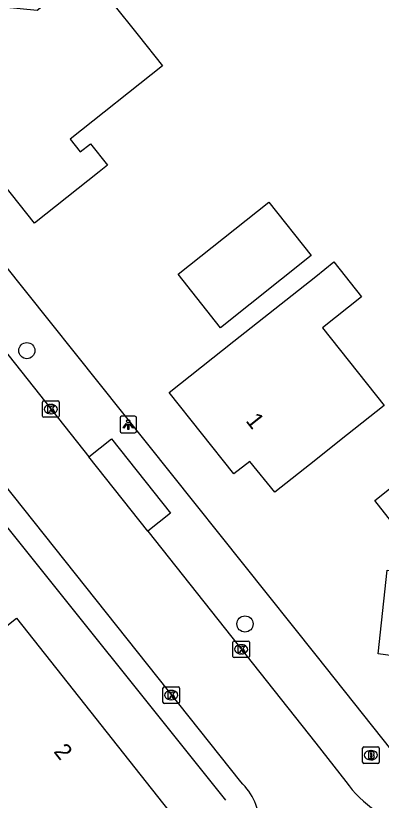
# Model space of a CAD drawing. Extents: x 159503 to 160347, y 382525 to 383272.
# Drawn here: x 159981.84 to 160003.97, y 383065.19 to 383112.66 of the extents above; entities that cross this region are included whole.
import ezdxf

# ---------------------------------------------------------------- set-up
doc = ezdxf.new("R2010")
doc.units = 0
for name, color, linetype in [('IMGEO_Boom', 7, 'Continuous'), ('IMGEO_Brandkraan', 7, 'Continuous'), ('IMGEO_Kolk', 7, 'Continuous'), ('IMGEO_Lichtpunt', 7, 'Continuous'), ('IMGEO_Pand', 7, 'Continuous'), ('IMGEO_Pand_nummerreeks', 7, 'Continuous'), ('IMGEO_Rijbaan_lokaal_open', 7, 'Continuous')]:
    doc.layers.add(name, color=color, linetype=linetype)

msp = doc.modelspace()

# ---------------------------------------------------------------- linework, layer by layer
at = {"layer": 'IMGEO_Boom'}
for centre in [(159982.51, 383092.398), (159995.72, 383075.858)]:
    msp.add_circle(centre, 0.489, dxfattribs=at)
at = {"layer": 'IMGEO_Brandkraan'}
for p, q in [((160002.843, 383067.49), (160002.843, 383068.342)), ((160002.918, 383068.416), (160003.77, 383068.416)), ((160003.331, 383068.196), (160003.356, 383068.196)), ((160003.844, 383068.342), (160003.844, 383067.49)), ((160003.354, 383067.636), (160003.329, 383067.636)), ((160003.77, 383067.416), (160002.918, 383067.416))]:
    msp.add_line(p, q, dxfattribs=at)
for points in [[(160002.843, 383067.49), (160002.843, 383068.342)], [(160002.918, 383068.416), (160003.77, 383068.416)], [(160003.191, 383068.116), (160003.191, 383067.716), (160003.404, 383067.716)], [(160003.422, 383068.116), (160003.191, 383068.116)], [(160003.844, 383068.342), (160003.844, 383067.49)], [(160003.37, 383068.035), (160003.316, 383068.035), (160003.316, 383067.959)], [(160003.316, 383067.959), (160003.369, 383067.959)], [(160003.378, 383067.883), (160003.316, 383067.883), (160003.316, 383067.802)], [(160003.316, 383067.802), (160003.378, 383067.802)], [(160003.77, 383067.416), (160002.918, 383067.416)]]:
    msp.add_lwpolyline(points, dxfattribs=at)
for centre, radius, start, end in [((160002.92, 383068.34), 0.0765, 91.552, 178.448), ((160002.92, 383068.34), 0.0765, 91.552, 178.448), ((160003.426, 383067.971), 0.145, 59.4692, 91.5367), ((160003.451, 383068.018), 0.0922, 285.5137, 58.1501), ((160003.768, 383068.34), 0.0765, 1.552, 88.448), ((160003.768, 383068.34), 0.0765, 1.552, 88.448), ((160003.371, 383067.997), 0.0379, 267.8285, 90.9355), ((160003.379, 383067.842), 0.0404, 269.8759, 90.5077), ((160003.41, 383067.967), 0.251, 268.6676, 293.5347), ((160003.456, 383067.826), 0.105, 301.3115, 78.989), ((160002.92, 383067.492), 0.0765, 181.552, 268.448), ((160002.92, 383067.492), 0.0765, 181.552, 268.448), ((160003.768, 383067.492), 0.0765, 271.552, 358.448), ((160003.768, 383067.492), 0.0765, 271.552, 358.448)]:
    msp.add_arc(centre, radius, start, end, dxfattribs=at)
for centre, major_axis, ratio, start_param, end_param in [((160003.33, 383067.916), (-0.387, 0.002), 0.722429, 4.712389, 7.853982), ((160003.355, 383067.916), (-0.39, 0.002), 0.717154, 1.570796, 4.712389)]:
    msp.add_ellipse(centre, major_axis=major_axis, ratio=ratio, start_param=start_param, end_param=end_param, dxfattribs=at)
at = {"layer": 'IMGEO_Kolk'}
for p, q in [((159983.465, 383088.436), (159983.465, 383089.288)), ((159983.54, 383089.362), (159984.392, 383089.362)), ((159983.953, 383089.142), (159983.978, 383089.142)), ((159984.466, 383089.288), (159984.466, 383088.436)), ((159983.976, 383088.582), (159983.951, 383088.582)), ((159984.392, 383088.362), (159983.54, 383088.362)), ((159994.991, 383073.898), (159994.991, 383074.75)), ((159995.066, 383074.824), (159995.918, 383074.824)), ((159995.992, 383074.75), (159995.992, 383073.898)), ((159995.479, 383074.604), (159995.504, 383074.604)), ((159995.918, 383073.824), (159995.066, 383073.824)), ((159995.502, 383074.044), (159995.477, 383074.044)), ((159990.754, 383071.127), (159990.754, 383071.979)), ((159990.829, 383072.053), (159991.681, 383072.053)), ((159991.755, 383071.979), (159991.755, 383071.127)), ((159991.242, 383071.833), (159991.267, 383071.833)), ((159991.681, 383071.053), (159990.829, 383071.053)), ((159991.265, 383071.273), (159991.24, 383071.273))]:
    msp.add_line(p, q, dxfattribs=at)
for points in [[(159983.465, 383088.436), (159983.465, 383089.288)], [(159983.54, 383089.362), (159984.392, 383089.362)], [(159983.786, 383089.062), (159983.909, 383089.062), (159983.909, 383088.911), (159984.039, 383089.062), (159984.203, 383089.062), (159984.057, 383088.911), (159984.21, 383088.662), (159984.058, 383088.662), (159983.973, 383088.826), (159983.909, 383088.759), (159983.909, 383088.662), (159983.786, 383088.662), (159983.786, 383089.062)], [(159984.466, 383089.288), (159984.466, 383088.436)], [(159984.392, 383088.362), (159983.54, 383088.362)], [(159994.991, 383073.898), (159994.991, 383074.75)], [(159995.066, 383074.824), (159995.918, 383074.824)], [(159995.992, 383074.75), (159995.992, 383073.898)], [(159995.312, 383074.524), (159995.435, 383074.524), (159995.435, 383074.373), (159995.565, 383074.524), (159995.729, 383074.524), (159995.583, 383074.373), (159995.736, 383074.124), (159995.584, 383074.124), (159995.499, 383074.288), (159995.435, 383074.221), (159995.435, 383074.124), (159995.312, 383074.124), (159995.312, 383074.524)], [(159995.918, 383073.824), (159995.066, 383073.824)], [(159990.754, 383071.127), (159990.754, 383071.979)], [(159990.829, 383072.053), (159991.681, 383072.053)], [(159991.755, 383071.979), (159991.755, 383071.127)], [(159991.075, 383071.753), (159991.198, 383071.753), (159991.198, 383071.602), (159991.328, 383071.753), (159991.492, 383071.753), (159991.346, 383071.602), (159991.499, 383071.353), (159991.347, 383071.353), (159991.262, 383071.517), (159991.198, 383071.45), (159991.198, 383071.353), (159991.075, 383071.353), (159991.075, 383071.753)], [(159991.681, 383071.053), (159990.829, 383071.053)]]:
    msp.add_lwpolyline(points, dxfattribs=at)
for centre, start, end in [((159983.542, 383089.286), 91.552, 178.448), ((159983.542, 383089.286), 91.552, 178.448), ((159984.39, 383089.286), 1.552, 88.448), ((159984.39, 383089.286), 1.552, 88.448), ((159983.542, 383088.438), 181.552, 268.448), ((159983.542, 383088.438), 181.552, 268.448), ((159984.39, 383088.438), 271.552, 358.448), ((159984.39, 383088.438), 271.552, 358.448), ((159995.068, 383074.748), 91.552, 178.448), ((159995.068, 383074.748), 91.552, 178.448), ((159995.916, 383074.748), 1.552, 88.448), ((159995.916, 383074.748), 1.552, 88.448), ((159995.068, 383073.9), 181.552, 268.448), ((159995.068, 383073.9), 181.552, 268.448), ((159995.916, 383073.9), 271.552, 358.448), ((159995.916, 383073.9), 271.552, 358.448), ((159990.831, 383071.977), 91.552, 178.448), ((159990.831, 383071.977), 91.552, 178.448), ((159991.679, 383071.977), 1.552, 88.448), ((159991.679, 383071.977), 1.552, 88.448), ((159990.831, 383071.129), 181.552, 268.448), ((159990.831, 383071.129), 181.552, 268.448), ((159991.679, 383071.129), 271.552, 358.448), ((159991.679, 383071.129), 271.552, 358.448)]:
    msp.add_arc(centre, 0.0765, start, end, dxfattribs=at)
for centre, major_axis, ratio, start_param, end_param in [((159983.952, 383088.862), (-0.387, 0.002), 0.722429, 4.712389, 7.853982), ((159983.977, 383088.862), (-0.39, 0.002), 0.717154, 1.570796, 4.712389), ((159995.478, 383074.324), (-0.387, 0.002), 0.722429, 4.712389, 7.853982), ((159995.503, 383074.324), (-0.39, 0.002), 0.717154, 1.570796, 4.712389), ((159991.241, 383071.553), (-0.387, 0.002), 0.722429, 4.712389, 7.853982), ((159991.266, 383071.553), (-0.39, 0.002), 0.717154, 1.570796, 4.712389)]:
    msp.add_ellipse(centre, major_axis=major_axis, ratio=ratio, start_param=start_param, end_param=end_param, dxfattribs=at)
at = {"layer": 'IMGEO_Lichtpunt'}
for p, q in [((159988.155, 383088.328), (159988.155, 383087.521)), ((159988.155, 383088.328), (159988.155, 383087.521)), ((159989.057, 383088.423), (159988.249, 383088.423)), ((159989.057, 383088.423), (159988.249, 383088.423)), ((159989.151, 383087.521), (159989.151, 383088.328)), ((159989.151, 383087.521), (159989.151, 383088.328)), ((159988.249, 383087.427), (159989.057, 383087.427)), ((159988.249, 383087.427), (159989.057, 383087.427))]:
    msp.add_line(p, q, dxfattribs=at)
for points in [[(159988.529, 383087.992), (159988.568, 383087.964), (159988.38, 383087.702), (159988.342, 383087.729), (159988.529, 383087.992)], [(159988.741, 383087.964), (159988.779, 383087.991), (159988.966, 383087.729), (159988.927, 383087.701), (159988.741, 383087.964)], [(159988.631, 383087.944), (159988.678, 383087.944), (159988.678, 383087.622), (159988.631, 383087.622), (159988.631, 383087.944)]]:
    msp.add_lwpolyline(points, dxfattribs=at)
msp.add_circle((159988.654, 383088.126), 0.0994, dxfattribs=at)
for centre, start, end in [((159988.249, 383088.328), 90, 180), ((159988.249, 383088.328), 90, 180), ((159989.057, 383088.328), 0, 90), ((159989.057, 383088.328), 0, 90), ((159988.249, 383087.521), 180, 270), ((159988.249, 383087.521), 180, 270), ((159989.057, 383087.521), 270, 0), ((159989.057, 383087.521), 270, 360)]:
    msp.add_arc(centre, 0.0946, start, end, dxfattribs=at)
at = {"layer": 'IMGEO_Pand'}
for points in [[(159990.718, 383109.639), (159985.126, 383105.184), (159985.737, 383104.418), (159986.361, 383104.917), (159987.389, 383103.626), (159986.881, 383103.221), (159982.971, 383100.104), (159980.091, 383103.717), (159980.599, 383104.122), (159978.131, 383107.219), (159977.63, 383106.82), (159973.87, 383111.54), (159978.65, 383115.3), (159980.233, 383113.288), (159983.128, 383112.99), (159986.139, 383115.388), (159989.255, 383111.477), (159990.718, 383109.639)], [(159994.232, 383093.785), (159991.67, 383097.02), (159997.172, 383101.379), (159999.734, 383098.144), (159994.232, 383093.785)], [(160004.152, 383089.074), (160001.451, 383086.935), (160000, 383085.786), (159997.531, 383083.83), (159996.02, 383085.698), (159995.048, 383084.943), (159991.134, 383089.869), (159995.054, 383092.974), (160000, 383096.892), (160001.098, 383097.761), (160002.775, 383095.644), (160000.423, 383093.78), (160004.152, 383089.074)], [(160011.843, 383085.728), (160013.657, 383085.494), (160013.102, 383080.419), (160012.189, 383080.526), (160012.019, 383078.201), (160013.746, 383076.102), (160011.54, 383074.345), (160007.652, 383071.248), (160005.568, 383073.804), (160003.777, 383074.045), (160004.319, 383079.118), (160005.233, 383079.064), (160005.425, 383080.99), (160003.591, 383083.329), (160007.496, 383086.453), (160009.78, 383088.28), (160011.843, 383085.728)], [(159981.882, 383076.202), (159991.799, 383063.691), (159985.573, 383058.726), (159984.982, 383059.41), (159982.494, 383057.437), (159979.38, 383061.349), (159978.579, 383062.354), (159979.762, 383063.296), (159976.547, 383067.334), (159977.876, 383068.392), (159975.603, 383071.247), (159977.958, 383073.105), (159981.882, 383076.202)]]:
    msp.add_lwpolyline(points, dxfattribs=at)
at = {"layer": 'IMGEO_Rijbaan_lokaal_open'}
for points in [[(159969.339, 383112.369), (160000, 383073.962), (160006.879, 383065.344), (160051.214, 383033.728), (160053.92, 383031.798)], [(159995.46, 383066.299), (159962.836, 383107.311)], [(159980.273, 383093.518), (159986.263, 383085.963)], [(159986.263, 383085.963), (159987.638, 383087.052), (159991.2, 383082.569), (159989.829, 383081.465)], [(159989.829, 383081.465), (159986.263, 383085.963)], [(159994.564, 383065.187), (159980.466, 383082.767)], [(159989.829, 383081.465), (160000, 383068.637), (160001.834, 383066.323)]]:
    msp.add_lwpolyline(points, dxfattribs=at)
for centre, radius, start, end in [((159992.986, 383063.631), 3.638, 0.4181, 47.1521), ((160006.929, 383069.78), 6.157, 214.1587, 237.8896)]:
    msp.add_arc(centre, radius, start, end, dxfattribs=at)

# ---------------------------------------------------------------- texts
at = {"layer": 'IMGEO_Pand_nummerreeks'}
for s, rotation, p in [('1', 308.4692, (159995.725, 383088.144)), ('2', 308.4052, (159984.098, 383068.126))]:
    msp.add_text(s, height=1, rotation=rotation, dxfattribs=at).set_placement(p)

doc.saveas('drawing.dxf')
